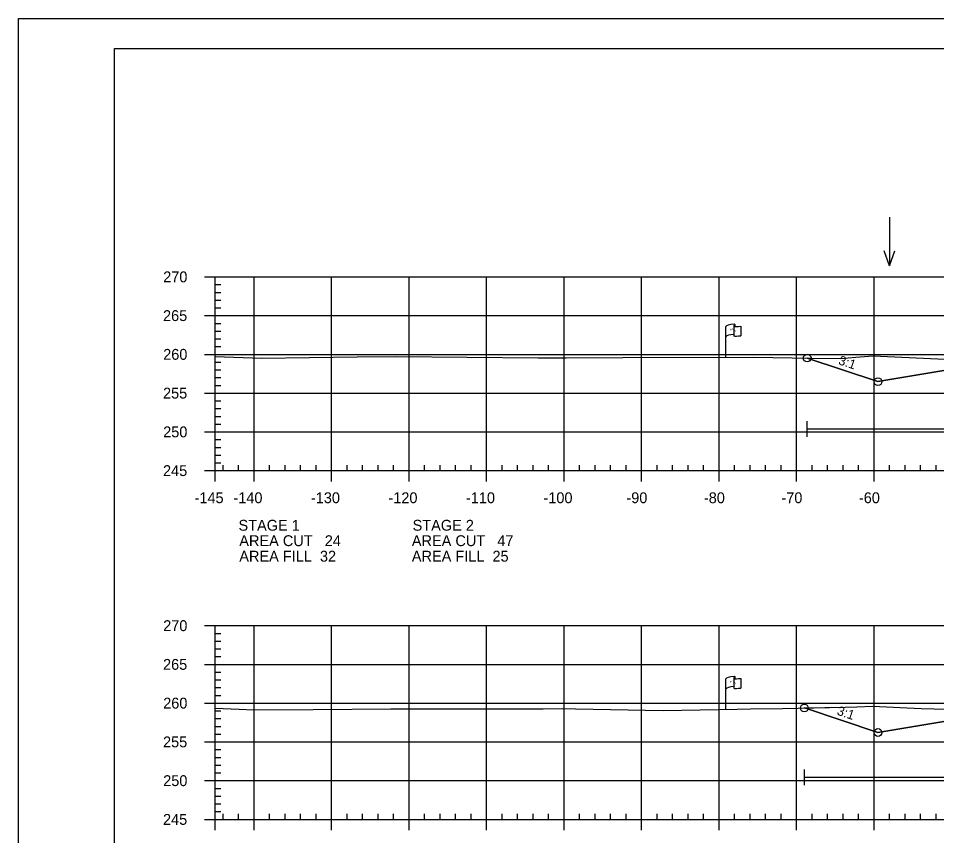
# Model space of a CAD drawing. Extents: x 1365647 to 1367999, y 387113 to 400173.
# Drawn here: x 1365723.7 to 1365842.2, y 387480.6 to 387586.1 of the extents above; entities that cross this region are included whole.
import ezdxf

# ---------------------------------------------------------------- set-up
doc = ezdxf.new("R2010")
doc.units = 0
for name, color, linetype in [('E_Existing ROW', 7, 'Continuous'), ('R_Axis', 7, 'Continuous'), ('R_Axis Annot', 7, 'Continuous'), ('R_Border', 7, 'Continuous'), ('R_Contours', 7, 'Continuous'), ('R_Exist Surface', 7, 'Continuous'), ('R_Fin Surface', 7, 'Continuous'), ('R_Fin Surface Annot', 7, 'Continuous'), ('R_Grid', 7, 'Continuous'), ('R_No Plot', 7, 'Continuous'), ('R_Proposed Const Limits', 7, 'Continuous'), ('R_Water', 7, 'Continuous'), ('R_Water Annot', 7, 'Continuous')]:
    doc.layers.add(name, color=color, linetype=linetype)

msp = doc.modelspace()

# ---------------------------------------------------------------- linework, layer by layer
at = {"layer": 'E_Existing ROW'}
for p, q in [((1365814.98, 387542.35), (1365814.98, 387546.3)), ((1365815.98, 387546.39), (1365815.98, 387546.38)), ((1365815.98, 387546.38), (1365815.98, 387545.15)), ((1365816.14, 387546.55), (1365816.14, 387546.31)), ((1365816.91, 387546.35), (1365816.91, 387545.11)), ((1365814.98, 387496.9), (1365814.98, 387500.85)), ((1365815.98, 387500.95), (1365815.98, 387500.93)), ((1365815.98, 387500.93), (1365815.98, 387499.71)), ((1365816.14, 387501.1), (1365816.14, 387500.86)), ((1365816.91, 387500.91), (1365816.91, 387499.67))]:
    msp.add_line(p, q, dxfattribs=at)
for centre, radius, start, end in [((1365816.05, 387546.39), 0.078, 88.6458, 274.2828), ((1365816.07, 387546.55), 0.0783, 263.0712, 93.9564), ((1365816.05, 387545.15), 0.0783, 180, 273.9564), ((1365816.05, 387500.95), 0.078, 88.6458, 274.2828), ((1365816.07, 387501.1), 0.0783, 263.0712, 93.9564), ((1365816.05, 387499.71), 0.0783, 180, 273.9564)]:
    msp.add_arc(centre, radius, start, end, dxfattribs=at)
for centre, major_axis, ratio, start_param, end_param in [((1365816.56, 387546.34), (-1.58, -0.04), 0.19887, 5.030368, 6.283185), ((1365817.27, 387546.46), (-1.23, -0.13), 0.052933, 0.159456, 1.268315), ((1365816.56, 387545.02), (-1.58, -0.04), 0.19887, 5.083035, 6.194897), ((1365817.27, 387545.22), (-1.23, -0.13), 0.052933, 0.159456, 1.268315), ((1365816.56, 387500.89), (-1.58, -0.04), 0.19887, 5.030368, 6.283185), ((1365817.27, 387501.01), (-1.23, -0.13), 0.052933, 0.159456, 1.268315), ((1365816.56, 387499.58), (-1.58, -0.04), 0.19887, 5.083035, 6.194897), ((1365817.27, 387499.77), (-1.23, -0.13), 0.052933, 0.159456, 1.268315)]:
    msp.add_ellipse(centre, major_axis=major_axis, ratio=ratio, start_param=start_param, end_param=end_param, dxfattribs=at)
at = {"layer": 'R_Axis'}
for p, q in [((1365747.69, 387552.72), (1365749.09, 387552.72)), ((1365749.09, 387527.72), (1365749.09, 387552.72)), ((1365749.09, 387551.72), (1365749.79, 387551.72)), ((1365749.09, 387550.72), (1365749.79, 387550.72)), ((1365749.09, 387549.72), (1365749.79, 387549.72)), ((1365749.09, 387548.72), (1365749.79, 387548.72)), ((1365747.69, 387547.72), (1365749.09, 387547.72)), ((1365749.09, 387546.72), (1365749.79, 387546.72)), ((1365749.09, 387545.72), (1365749.79, 387545.72)), ((1365749.09, 387544.72), (1365749.79, 387544.72)), ((1365749.09, 387543.72), (1365749.79, 387543.72)), ((1365747.69, 387542.72), (1365749.09, 387542.72)), ((1365749.09, 387541.72), (1365749.79, 387541.72)), ((1365749.09, 387540.72), (1365749.79, 387540.72)), ((1365749.09, 387539.72), (1365749.79, 387539.72)), ((1365749.09, 387538.72), (1365749.79, 387538.72)), ((1365747.69, 387537.72), (1365749.09, 387537.72)), ((1365749.09, 387536.72), (1365749.79, 387536.72)), ((1365749.09, 387535.72), (1365749.79, 387535.72)), ((1365749.09, 387534.72), (1365749.79, 387534.72)), ((1365747.69, 387532.72), (1365749.09, 387532.72)), ((1365749.09, 387533.72), (1365749.79, 387533.72)), ((1365749.09, 387531.72), (1365749.79, 387531.72)), ((1365749.09, 387530.72), (1365749.79, 387530.72)), ((1365749.09, 387529.72), (1365749.79, 387529.72)), ((1365749.09, 387528.72), (1365749.79, 387528.72)), ((1365749.09, 387527.72), (1365749.09, 387528.42)), ((1365750.09, 387527.72), (1365750.09, 387528.42)), ((1365752.09, 387527.72), (1365752.09, 387528.42)), ((1365756.09, 387527.72), (1365756.09, 387528.42)), ((1365758.09, 387527.72), (1365758.09, 387528.42)), ((1365760.09, 387527.72), (1365760.09, 387528.42)), ((1365762.09, 387527.72), (1365762.09, 387528.42)), ((1365766.09, 387527.72), (1365766.09, 387528.42)), ((1365768.09, 387527.72), (1365768.09, 387528.42)), ((1365770.09, 387527.72), (1365770.09, 387528.42)), ((1365772.09, 387527.72), (1365772.09, 387528.42)), ((1365776.09, 387527.72), (1365776.09, 387528.42)), ((1365778.09, 387527.72), (1365778.09, 387528.42)), ((1365780.09, 387527.72), (1365780.09, 387528.42)), ((1365782.09, 387527.72), (1365782.09, 387528.42)), ((1365786.09, 387527.72), (1365786.09, 387528.42)), ((1365788.09, 387527.72), (1365788.09, 387528.42)), ((1365790.09, 387527.72), (1365790.09, 387528.42)), ((1365792.09, 387527.72), (1365792.09, 387528.42)), ((1365796.09, 387527.72), (1365796.09, 387528.42)), ((1365798.09, 387527.72), (1365798.09, 387528.42)), ((1365800.09, 387527.72), (1365800.09, 387528.42)), ((1365802.09, 387527.72), (1365802.09, 387528.42)), ((1365806.09, 387527.72), (1365806.09, 387528.42)), ((1365808.09, 387527.72), (1365808.09, 387528.42)), ((1365810.09, 387527.72), (1365810.09, 387528.42)), ((1365812.09, 387527.72), (1365812.09, 387528.42)), ((1365816.09, 387527.72), (1365816.09, 387528.42)), ((1365818.09, 387527.72), (1365818.09, 387528.42)), ((1365820.09, 387527.72), (1365820.09, 387528.42)), ((1365822.09, 387527.72), (1365822.09, 387528.42)), ((1365826.09, 387527.72), (1365826.09, 387528.42)), ((1365828.09, 387527.72), (1365828.09, 387528.42)), ((1365830.09, 387527.72), (1365830.09, 387528.42)), ((1365832.09, 387527.72), (1365832.09, 387528.42)), ((1365836.09, 387527.72), (1365836.09, 387528.42)), ((1365838.09, 387527.72), (1365838.09, 387528.42)), ((1365840.09, 387527.72), (1365840.09, 387528.42)), ((1365842.09, 387527.72), (1365842.09, 387528.42)), ((1365747.69, 387527.72), (1365749.09, 387527.72)), ((1365749.09, 387527.72), (1366039.09, 387527.72)), ((1365749.09, 387526.32), (1365749.09, 387527.72)), ((1365754.09, 387526.32), (1365754.09, 387527.72)), ((1365764.09, 387526.32), (1365764.09, 387527.72)), ((1365774.09, 387526.32), (1365774.09, 387527.72)), ((1365784.09, 387526.32), (1365784.09, 387527.72)), ((1365794.09, 387526.32), (1365794.09, 387527.72)), ((1365804.09, 387526.32), (1365804.09, 387527.72)), ((1365814.09, 387526.32), (1365814.09, 387527.72)), ((1365824.09, 387526.32), (1365824.09, 387527.72)), ((1365834.09, 387526.32), (1365834.09, 387527.72)), ((1365747.69, 387507.72), (1365749.09, 387507.72)), ((1365749.09, 387482.72), (1365749.09, 387507.72)), ((1365749.09, 387506.72), (1365749.79, 387506.72)), ((1365749.09, 387505.72), (1365749.79, 387505.72)), ((1365749.09, 387504.72), (1365749.79, 387504.72)), ((1365749.09, 387503.72), (1365749.79, 387503.72)), ((1365747.69, 387502.72), (1365749.09, 387502.72)), ((1365749.09, 387501.72), (1365749.79, 387501.72)), ((1365749.09, 387500.72), (1365749.79, 387500.72)), ((1365749.09, 387499.72), (1365749.79, 387499.72)), ((1365749.09, 387498.72), (1365749.79, 387498.72)), ((1365747.69, 387497.72), (1365749.09, 387497.72)), ((1365749.09, 387496.72), (1365749.79, 387496.72)), ((1365749.09, 387495.72), (1365749.79, 387495.72)), ((1365749.09, 387494.72), (1365749.79, 387494.72)), ((1365749.09, 387493.72), (1365749.79, 387493.72)), ((1365747.69, 387492.72), (1365749.09, 387492.72)), ((1365749.09, 387491.72), (1365749.79, 387491.72)), ((1365749.09, 387490.72), (1365749.79, 387490.72)), ((1365749.09, 387489.72), (1365749.79, 387489.72)), ((1365747.69, 387487.72), (1365749.09, 387487.72)), ((1365749.09, 387488.72), (1365749.79, 387488.72)), ((1365749.09, 387486.72), (1365749.79, 387486.72)), ((1365749.09, 387485.72), (1365749.79, 387485.72)), ((1365749.09, 387484.72), (1365749.79, 387484.72)), ((1365749.09, 387483.72), (1365749.79, 387483.72)), ((1365749.09, 387482.72), (1365749.09, 387483.42)), ((1365750.09, 387482.72), (1365750.09, 387483.42)), ((1365752.09, 387482.72), (1365752.09, 387483.42)), ((1365756.09, 387482.72), (1365756.09, 387483.42)), ((1365758.09, 387482.72), (1365758.09, 387483.42)), ((1365760.09, 387482.72), (1365760.09, 387483.42)), ((1365762.09, 387482.72), (1365762.09, 387483.42)), ((1365766.09, 387482.72), (1365766.09, 387483.42)), ((1365768.09, 387482.72), (1365768.09, 387483.42)), ((1365770.09, 387482.72), (1365770.09, 387483.42)), ((1365772.09, 387482.72), (1365772.09, 387483.42)), ((1365776.09, 387482.72), (1365776.09, 387483.42)), ((1365778.09, 387482.72), (1365778.09, 387483.42)), ((1365780.09, 387482.72), (1365780.09, 387483.42)), ((1365782.09, 387482.72), (1365782.09, 387483.42)), ((1365786.09, 387482.72), (1365786.09, 387483.42)), ((1365788.09, 387482.72), (1365788.09, 387483.42)), ((1365790.09, 387482.72), (1365790.09, 387483.42)), ((1365792.09, 387482.72), (1365792.09, 387483.42)), ((1365796.09, 387482.72), (1365796.09, 387483.42)), ((1365798.09, 387482.72), (1365798.09, 387483.42)), ((1365800.09, 387482.72), (1365800.09, 387483.42)), ((1365802.09, 387482.72), (1365802.09, 387483.42)), ((1365806.09, 387482.72), (1365806.09, 387483.42)), ((1365808.09, 387482.72), (1365808.09, 387483.42)), ((1365810.09, 387482.72), (1365810.09, 387483.42)), ((1365812.09, 387482.72), (1365812.09, 387483.42)), ((1365816.09, 387482.72), (1365816.09, 387483.42)), ((1365818.09, 387482.72), (1365818.09, 387483.42)), ((1365820.09, 387482.72), (1365820.09, 387483.42)), ((1365822.09, 387482.72), (1365822.09, 387483.42)), ((1365826.09, 387482.72), (1365826.09, 387483.42)), ((1365828.09, 387482.72), (1365828.09, 387483.42)), ((1365830.09, 387482.72), (1365830.09, 387483.42)), ((1365832.09, 387482.72), (1365832.09, 387483.42)), ((1365836.09, 387482.72), (1365836.09, 387483.42)), ((1365838.09, 387482.72), (1365838.09, 387483.42)), ((1365840.09, 387482.72), (1365840.09, 387483.42)), ((1365842.09, 387482.72), (1365842.09, 387483.42)), ((1365747.69, 387482.72), (1365749.09, 387482.72)), ((1365749.09, 387482.72), (1366039.09, 387482.72)), ((1365749.09, 387481.32), (1365749.09, 387482.72)), ((1365754.09, 387481.32), (1365754.09, 387482.72)), ((1365764.09, 387481.32), (1365764.09, 387482.72)), ((1365774.09, 387481.32), (1365774.09, 387482.72)), ((1365784.09, 387481.32), (1365784.09, 387482.72)), ((1365794.09, 387481.32), (1365794.09, 387482.72)), ((1365804.09, 387481.32), (1365804.09, 387482.72)), ((1365814.09, 387481.32), (1365814.09, 387482.72)), ((1365824.09, 387481.32), (1365824.09, 387482.72)), ((1365834.09, 387481.32), (1365834.09, 387482.72))]:
    msp.add_line(p, q, dxfattribs=at)
at = {"layer": 'R_Border'}
for p, q in [((1365736.09, 387582.18), (1366052.27, 387582.18)), ((1365736.09, 387376.72), (1365736.09, 387582.18))]:
    msp.add_line(p, q, dxfattribs=at)
at = {"layer": 'R_Contours'}
for points in [[(1365825.46, 387542.24), (1365826.05, 387542.23), (1365829.75, 387542.2), (1365831.75, 387542.34), (1365833.96, 387542.52), (1365842.3, 387542.16), (1365844.65, 387542.06), (1365847.92, 387541.58), (1365849.26, 387541.38), (1365847.47, 387541.35), (1365834.59, 387539.2)], [(1365825.09, 387497.1), (1365830.36, 387497.22), (1365831.85, 387497.24), (1365833.88, 387497.31), (1365840.18, 387497.02), (1365845.22, 387496.92), (1365850.26, 387496.13), (1365847.47, 387496.08), (1365834.59, 387493.93)]]:
    msp.add_lwpolyline(points, close=True, dxfattribs=at)
at = {"layer": 'R_Exist Surface'}
for points in [[(1365749.09, 387542.43), (1365755.1, 387542.25), (1365767.4, 387542.39), (1365772.42, 387542.43), (1365790.74, 387542.27), (1365794.35, 387542.28), (1365801.69, 387542.3), (1365818.49, 387542.36), (1365826.05, 387542.23), (1365829.75, 387542.2), (1365831.75, 387542.34), (1365833.96, 387542.52), (1365842.3, 387542.16)], [(1365749.09, 387497.09), (1365752.16, 387496.94), (1365754.02, 387496.84), (1365761.72, 387496.92), (1365771.76, 387496.99), (1365791.4, 387497), (1365793.87, 387497.02), (1365795.58, 387496.98), (1365806.86, 387496.76), (1365816.42, 387496.93), (1365818.15, 387496.97), (1365822.27, 387497.03), (1365830.36, 387497.22), (1365831.85, 387497.24), (1365833.88, 387497.31), (1365840.18, 387497.02), (1365845.22, 387496.92)]]:
    msp.add_lwpolyline(points, dxfattribs=at)
at = {"layer": 'R_Fin Surface'}
for points in [[(1365825.46, 387542.24), (1365834.59, 387539.2), (1365847.47, 387541.35), (1365856.59, 387542.87), (1365862.59, 387543.11), (1365864.59, 387543.15), (1365894.09, 387543.74), (1365923.59, 387543.15), (1365925.59, 387543.11), (1365931.59, 387542.87), (1365940.72, 387541.35), (1365953.59, 387539.2), (1365959.38, 387541.13)], [(1365825.09, 387497.1), (1365834.59, 387493.93), (1365847.47, 387496.08), (1365856.59, 387497.6), (1365862.59, 387497.84), (1365864.59, 387497.88), (1365894.09, 387498.47), (1365923.59, 387497.88), (1365925.59, 387497.84), (1365931.59, 387497.6), (1365940.72, 387496.08), (1365953.59, 387493.93), (1365958.16, 387495.45)]]:
    msp.add_lwpolyline(points, dxfattribs=at)
at = {"layer": 'R_Grid'}
for p, q in [((1365749.09, 387552.72), (1366039.09, 387552.72)), ((1365749.09, 387527.72), (1365749.09, 387552.72)), ((1365754.09, 387527.72), (1365754.09, 387552.72)), ((1365764.09, 387527.72), (1365764.09, 387552.72)), ((1365774.09, 387527.72), (1365774.09, 387552.72)), ((1365784.09, 387527.72), (1365784.09, 387552.72)), ((1365794.09, 387527.72), (1365794.09, 387552.72)), ((1365804.09, 387527.72), (1365804.09, 387552.72)), ((1365814.09, 387527.72), (1365814.09, 387552.72)), ((1365824.09, 387527.72), (1365824.09, 387552.72)), ((1365834.09, 387527.72), (1365834.09, 387552.72)), ((1365749.09, 387547.72), (1366039.09, 387547.72)), ((1365749.09, 387542.72), (1366039.09, 387542.72)), ((1365749.09, 387537.72), (1366039.09, 387537.72)), ((1365749.09, 387532.72), (1366039.09, 387532.72)), ((1365749.09, 387527.72), (1366039.09, 387527.72)), ((1365749.09, 387507.72), (1366039.09, 387507.72)), ((1365749.09, 387482.72), (1365749.09, 387507.72)), ((1365754.09, 387482.72), (1365754.09, 387507.72)), ((1365764.09, 387482.72), (1365764.09, 387507.72)), ((1365774.09, 387482.72), (1365774.09, 387507.72)), ((1365784.09, 387482.72), (1365784.09, 387507.72)), ((1365794.09, 387482.72), (1365794.09, 387507.72)), ((1365804.09, 387482.72), (1365804.09, 387507.72)), ((1365814.09, 387482.72), (1365814.09, 387507.72)), ((1365824.09, 387482.72), (1365824.09, 387507.72)), ((1365834.09, 387482.72), (1365834.09, 387507.72)), ((1365749.09, 387502.72), (1366039.09, 387502.72)), ((1365749.09, 387497.72), (1366039.09, 387497.72)), ((1365749.09, 387492.72), (1366039.09, 387492.72)), ((1365749.09, 387487.72), (1366039.09, 387487.72)), ((1365749.09, 387482.72), (1366039.09, 387482.72))]:
    msp.add_line(p, q, dxfattribs=at)
at = {"layer": 'R_No Plot'}
msp.add_line((1365723.69, 387586.07), (1366057.03, 387586.07), dxfattribs=at)
msp.add_lwpolyline([(1365723.69, 387586.07), (1366057.03, 387586.07), (1366057.03, 387372.73), (1365723.69, 387372.73)], close=True, dxfattribs=at)
for centre in [(1365825.46, 387542.24), (1365825.46, 387542.24), (1365834.59, 387539.2), (1365834.59, 387539.2), (1365834.59, 387539.2), (1365834.59, 387539.2), (1365834.59, 387539.2), (1365825.09, 387497.1), (1365825.09, 387497.1), (1365834.59, 387493.93), (1365834.59, 387493.93), (1365834.59, 387493.93), (1365834.59, 387493.93), (1365834.59, 387493.93)]:
    msp.add_circle(centre, 0.5, dxfattribs=at)
at = {"layer": 'R_Proposed Const Limits'}
for points in [[(1365856.59, 387542.87), (1365834.59, 387539.2), (1365825.46, 387542.24)], [(1365856.59, 387497.6), (1365834.59, 387493.93), (1365825.09, 387497.1)]]:
    msp.add_lwpolyline(points, dxfattribs=at)
at = {"layer": 'R_Water'}
for p, q in [((1365825.46, 387532.1), (1365825.46, 387534.1)), ((1365825.46, 387533.1), (1365882.71, 387533.1)), ((1365825.09, 387487.15), (1365825.09, 387489.15)), ((1365825.09, 387488.15), (1365882.52, 387488.15))]:
    msp.add_line(p, q, dxfattribs=at)
at = {"layer": 'R_Water Annot'}
for p, q in [((1365836.08, 387560.42), (1365836.08, 387554.14)), ((1365836.08, 387554.14), (1365835.38, 387556.06)), ((1365836.08, 387554.14), (1365836.78, 387556.06))]:
    msp.add_line(p, q, dxfattribs=at)

# ---------------------------------------------------------------- texts
at = {"layer": 'E_Existing ROW'}
for s, height, rotation, p in [('R ', 0.2, 9.9884, (1365815.5, 387545.8)), (' O', 0.2, 9.9884, (1365815.65, 387545.84)), ('W', 0.2, 351.1788, (1365815.98, 387545.68)), ('DWB 11-9-07', 0.001, 90, (1365816.14, 387546.31)), ('DWB 11-9-07', 0.001, 5.0717, (1365816.9, 387545.11)), ('DWB 11-9-07', 0.001, 90, (1365814.98, 387542.35)), ('DWB 11-9-07', 0.001, 90, (1365816.14, 387500.86)), ('R ', 0.2, 9.9884, (1365815.5, 387500.35)), (' O', 0.2, 9.9884, (1365815.65, 387500.4)), ('W', 0.2, 351.1788, (1365815.98, 387500.23)), ('DWB 11-9-07', 0.001, 5.0717, (1365816.9, 387499.67)), ('DWB 11-9-07', 0.001, 90, (1365814.98, 387496.9))]:
    msp.add_text(s, height=height, rotation=rotation, dxfattribs=at).set_placement(p)
at = {"layer": 'R_Axis Annot'}
for s, p in [('270', (1365742.37, 387552.02)), ('265', (1365742.35, 387547.02)), ('260', (1365742.37, 387542.02)), ('255', (1365742.35, 387537.02)), ('250', (1365742.37, 387532.02)), ('245', (1365742.35, 387527.02)), ('-145', (1365746.42, 387523.52)), ('-140', (1365751.43, 387523.52)), ('-130', (1365761.43, 387523.52)), ('-120', (1365771.43, 387523.52)), ('-110', (1365781.43, 387523.52)), ('-100', (1365791.43, 387523.52)), ('-90', (1365802.13, 387523.52)), ('-80', (1365812.13, 387523.52)), ('-70', (1365822.13, 387523.52)), ('-60', (1365832.13, 387523.52)), ('STAGE 1', (1365752.09, 387519.97)), ('STAGE 2', (1365774.55, 387519.97)), ('AREA CUT   24', (1365752.19, 387517.98)), ('AREA CUT   47', (1365774.45, 387517.98)), ('AREA FILL  32', (1365752.19, 387515.98)), ('AREA FILL  25', (1365774.45, 387515.98)), ('270', (1365742.37, 387507.02)), ('265', (1365742.35, 387502.02)), ('260', (1365742.37, 387497.02)), ('255', (1365742.35, 387492.02)), ('250', (1365742.37, 387487.02)), ('245', (1365742.35, 387482.02))]:
    msp.add_text(s, height=1.4, dxfattribs=at).set_placement(p)
at = {"layer": 'R_Fin Surface Annot'}
for rotation, p in [(341.5651, (1365829.4, 387541.46)), (341.5657, (1365829.4, 387541.46)), (341.5651, (1365829.21, 387496.25)), (341.5642, (1365829.21, 387496.25))]:
    msp.add_text('3:1', height=1.2, rotation=rotation, dxfattribs=at).set_placement(p)

doc.saveas('drawing.dxf')
